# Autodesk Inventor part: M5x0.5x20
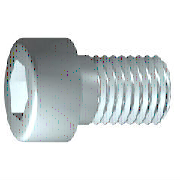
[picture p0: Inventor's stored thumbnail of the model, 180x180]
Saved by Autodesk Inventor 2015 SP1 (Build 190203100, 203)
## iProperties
IsCustomPart: 0
Company: 한국ATC센터
Created: 2014-07
Part Number: M5x0.5x20
Material: Steel, Mild
Description: 6각머리 태핑 나사
Document SubType Name: Modeling
Standard: KS B 1003
Designer: KYOUNG IL JANG
Standards Organization: KS
Language: ko-KR
Size Designation: M 5 x 20
Categories: <MemberInstance><Categories><Category DisplayName="조임쇠" InternalName="e4da775c-781d-43d5-af7c-5136215cf5a6" Mnemonic="FSTN"><Category DisplayName="볼트" InternalN
Density: 7.86 g/cm^3
Appearance: Metal-Steel
Mass: 4.9629 g
Surface Area: 5.88237 cm^2
Volume: 0.631412 cm^3
Author: KYOUNG IL JANG
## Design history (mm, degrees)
sketch "스케치1"
  geometry: L1 (-1.167, 0)-(20, 0); L2 (20, 0)-(20, 2.5); L3 (20, 2.5)-(2, 2.5); L4 (2, 2.5)-(1.509, 2.5); L5 (1.509, 2.5)-(0, 2.5); L6 (0, 2.5)-(0, 4.25); L7 (0, 4.25)-(-5, 4.25); L8 (-5, 4.25)-(-5, 2.309); L9 (-5, 2.309)-(-2.5, 2.309); L10 (-2.5, 2.309)-(-1.167, 0); L11 (-10, 0)-(25, 0) reference; L12 (0, -0.85)-(0, 5.1) reference; L13 (2, 2.5)-(0, 2.5)
  constraints: 22 end point, 6 parallel, 2 collinear, 2 perpendicular, 1 horizontal, 1 point on line
  dimensions: "d1" = 18 distance from line of L3.end L2 (= GEL); "d2" = 0.49086 distance of L4.end L3.end (computed from GAL); "d3" = 5 distance between parallel lines of L8 L6 (= KOH); "d4" = 2.5 distance of L8.end L9.end (= INTI); "d5" = 60 deg angle of L10 L1; "d6" = 5 diameter of L3 L1 (= GD); "d7" = 5 diameter of L5 L1 (= BDM); "d8" = 4.6188 diameter of L9 L1 (= 1.1547 x SW); "d9" = 8.5 diameter of L7 L1 (= KOD); "d26" = 20 distance between parallel lines of L12 L2 (= NLG)
revolve "본체" sketch "스케치1" stored, may be unused: angle "d10" = 90 deg
sketch "스케치2"
  geometry: L1 (0, -5.95)-(0, 5.95) reference; L2 (-5.95, 0)-(5.95, 0) reference; L3 (2.309, 0)-(1.155, -2); L4 (1.155, -2)-(-1.155, -2); L5 (-1.155, -2)-(-2.309, 0); L6 (-2.309, 0)-(-1.155, 2); L7 (-1.155, 2)-(1.155, 2); L8 (1.155, 2)-(2.309, 0); 2 further points
  constraints: 12 end point, 1 coincident, 1 horizontal alignment, 1 point on line, 12 other
extrude "슬롯" join sketch "스케치2" stored distance "d11" = 10; taper "d12" = 0 deg
workplane "Work Plane1"
fillet "Fillet2" dims "d30" = 0.1 (= R)
body "Solid1"
fillet "모깎기1" dims "d17" = 0.5 (= RR)
feature "스레드" dims "d13" = 18 (= GEL), "d14" = 0
chamfer "모따기1" distance "d15" = 0.49076 (= -0.5 x SPD + 0.5 x GD); stored, may be unused: second distance "d16" = 0.49076 (= GUL), angle "d27" = 45 deg
other parameters: "GD" = 5 (= NND) [user parameter; used in 2 equation terms], "NLG" = 20 [user parameter; used in 1 equation term], "GEL" = 18 [user parameter; used in 2 equation terms], "KOD" = 8.5 [user parameter; used in 1 equation term], "KOH" = 5 [user parameter; used in 1 equation term], "INTI" = 2.5 [user parameter; used in 1 equation term], "GAL" = 0.49076 (= 0.61345 x PTC) [user parameter; used in 1 equation term], "GUL" = 0.49076 (= 0.61345 x PTC) [user parameter; used in 1 equation term], "BDM" = 5 (= NND) [user parameter; used in 1 equation term], "SW" = 4 [user parameter; used in 2 equation terms], "RR" = 0.5 [user parameter; used in 1 equation term], "SPD" = 4.01848 (= NND - 1.2269 x PTC) [user parameter; used in 1 equation term], "d19" = 0, "d28" = 0, "d29" = 0, "R" = 0.1 [user parameter; used in 1 equation term], "PHH" = 0.2 [user parameter], "GD1" = 4.01848 (= THREADDIA - 1.2269 x PTC) [user parameter], "THREADDIA" = 5 [user parameter; used in 1 equation term], "FAWI" = 45 deg [user parameter], "TPU" = 12.5 (computed from PTC) [user parameter], "PTC" = 0.8 [user parameter; used in 5 equation terms], "NND" = 5 [user parameter; used in 3 equation terms], "TOA" = 30 deg [user parameter], "E0" = 4.62 (= 1.155 x SW) [user parameter]
